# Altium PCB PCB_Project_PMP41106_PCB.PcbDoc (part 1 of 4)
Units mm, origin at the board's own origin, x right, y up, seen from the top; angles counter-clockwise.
Board outline 190 x 100 mm, 2 copper layers (Top Layer, Bottom Layer), stack 1.646 mm thick; 219 components, 122 nets, 541 pads, 61 vias.
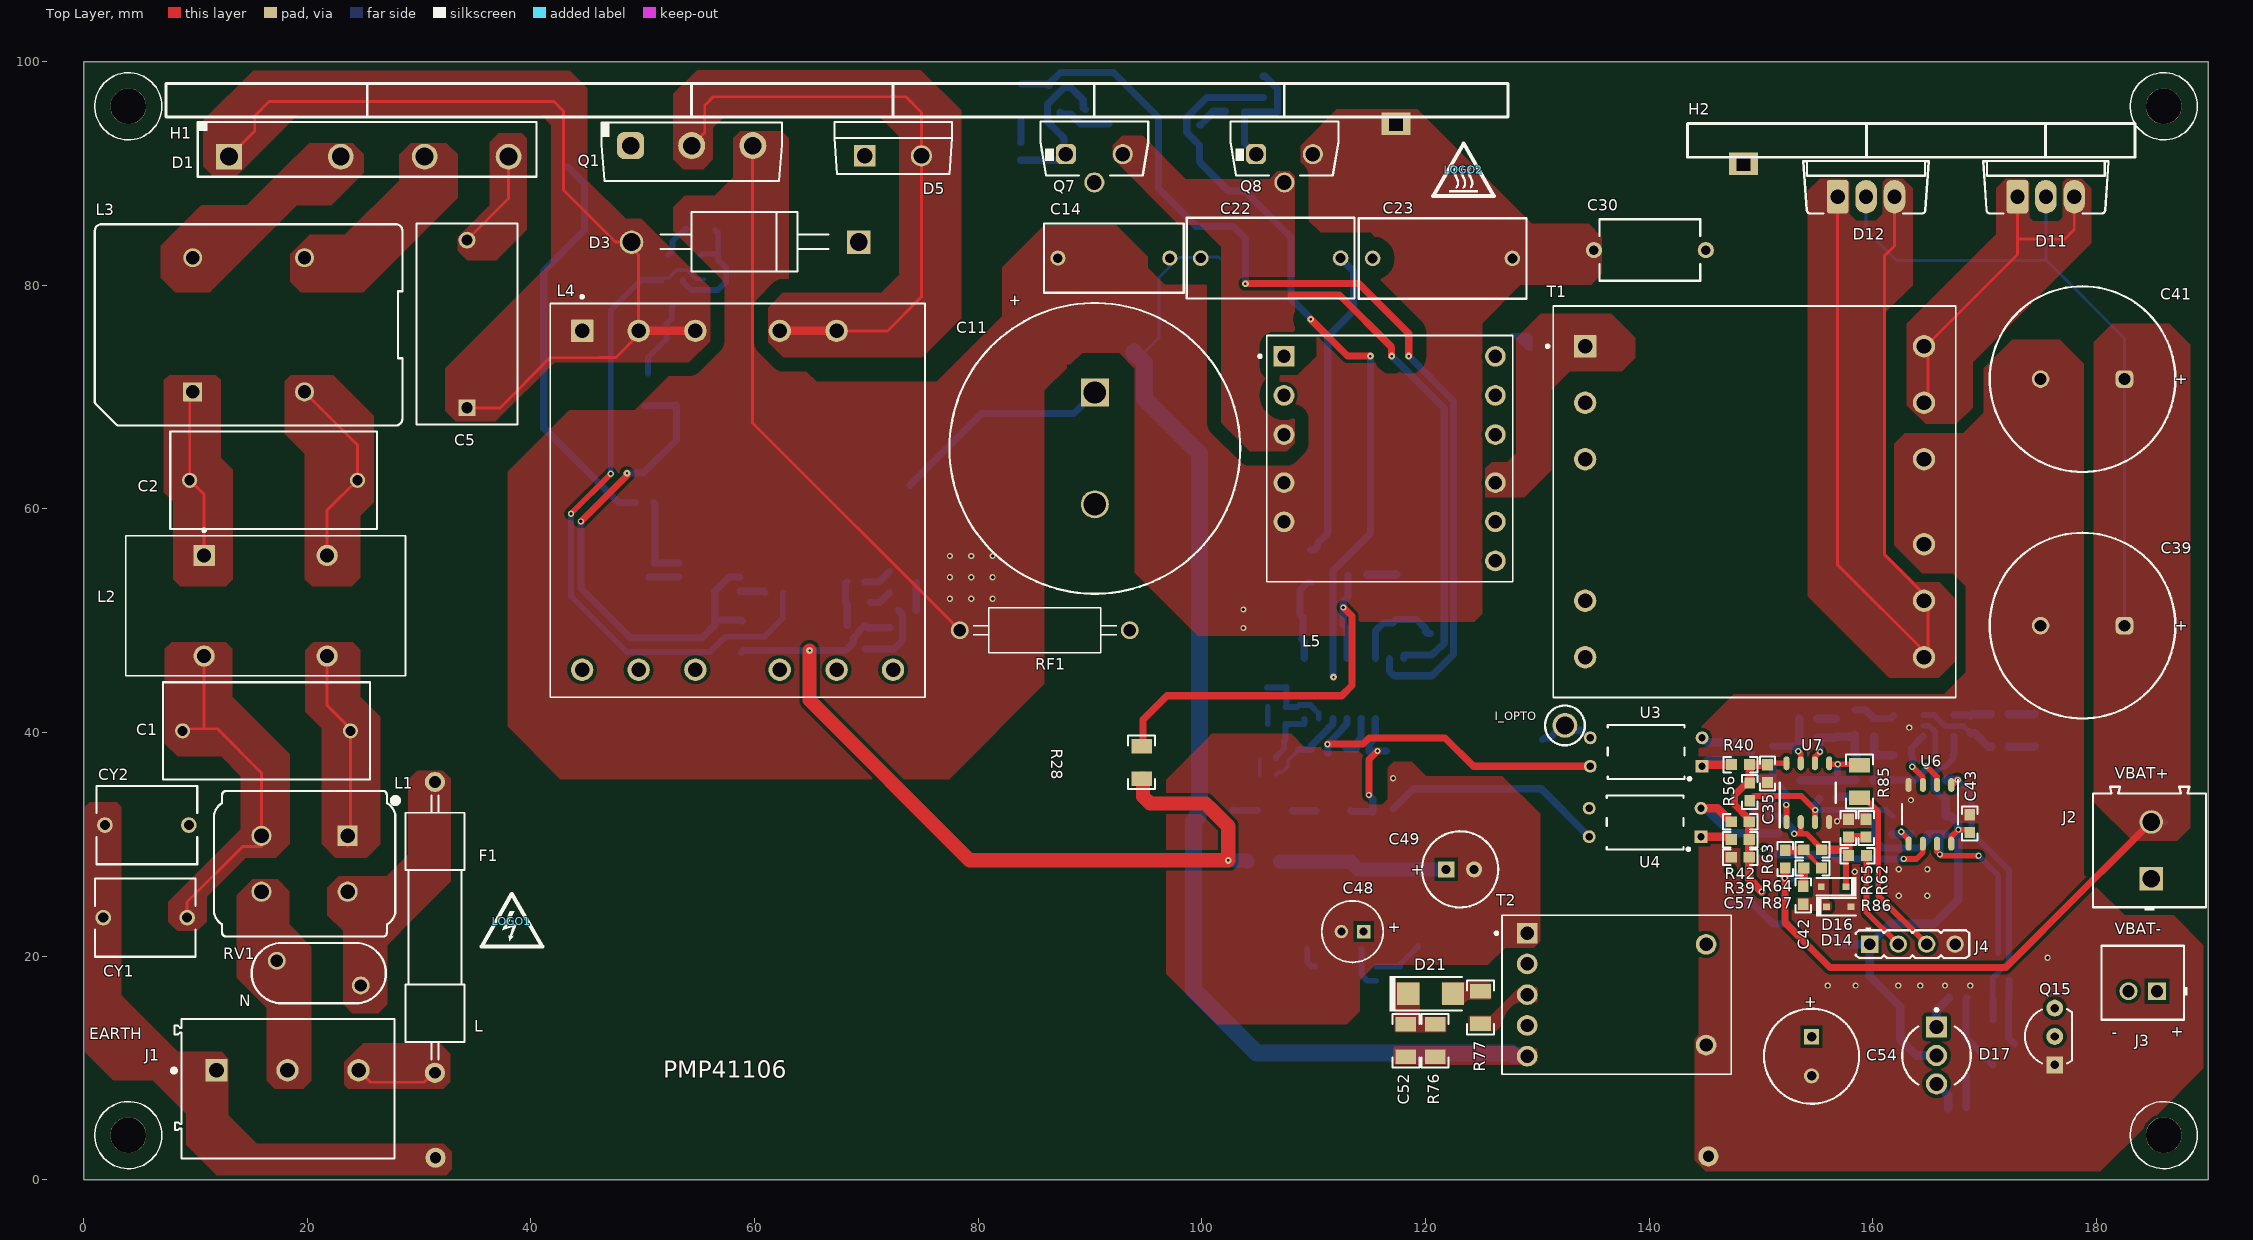
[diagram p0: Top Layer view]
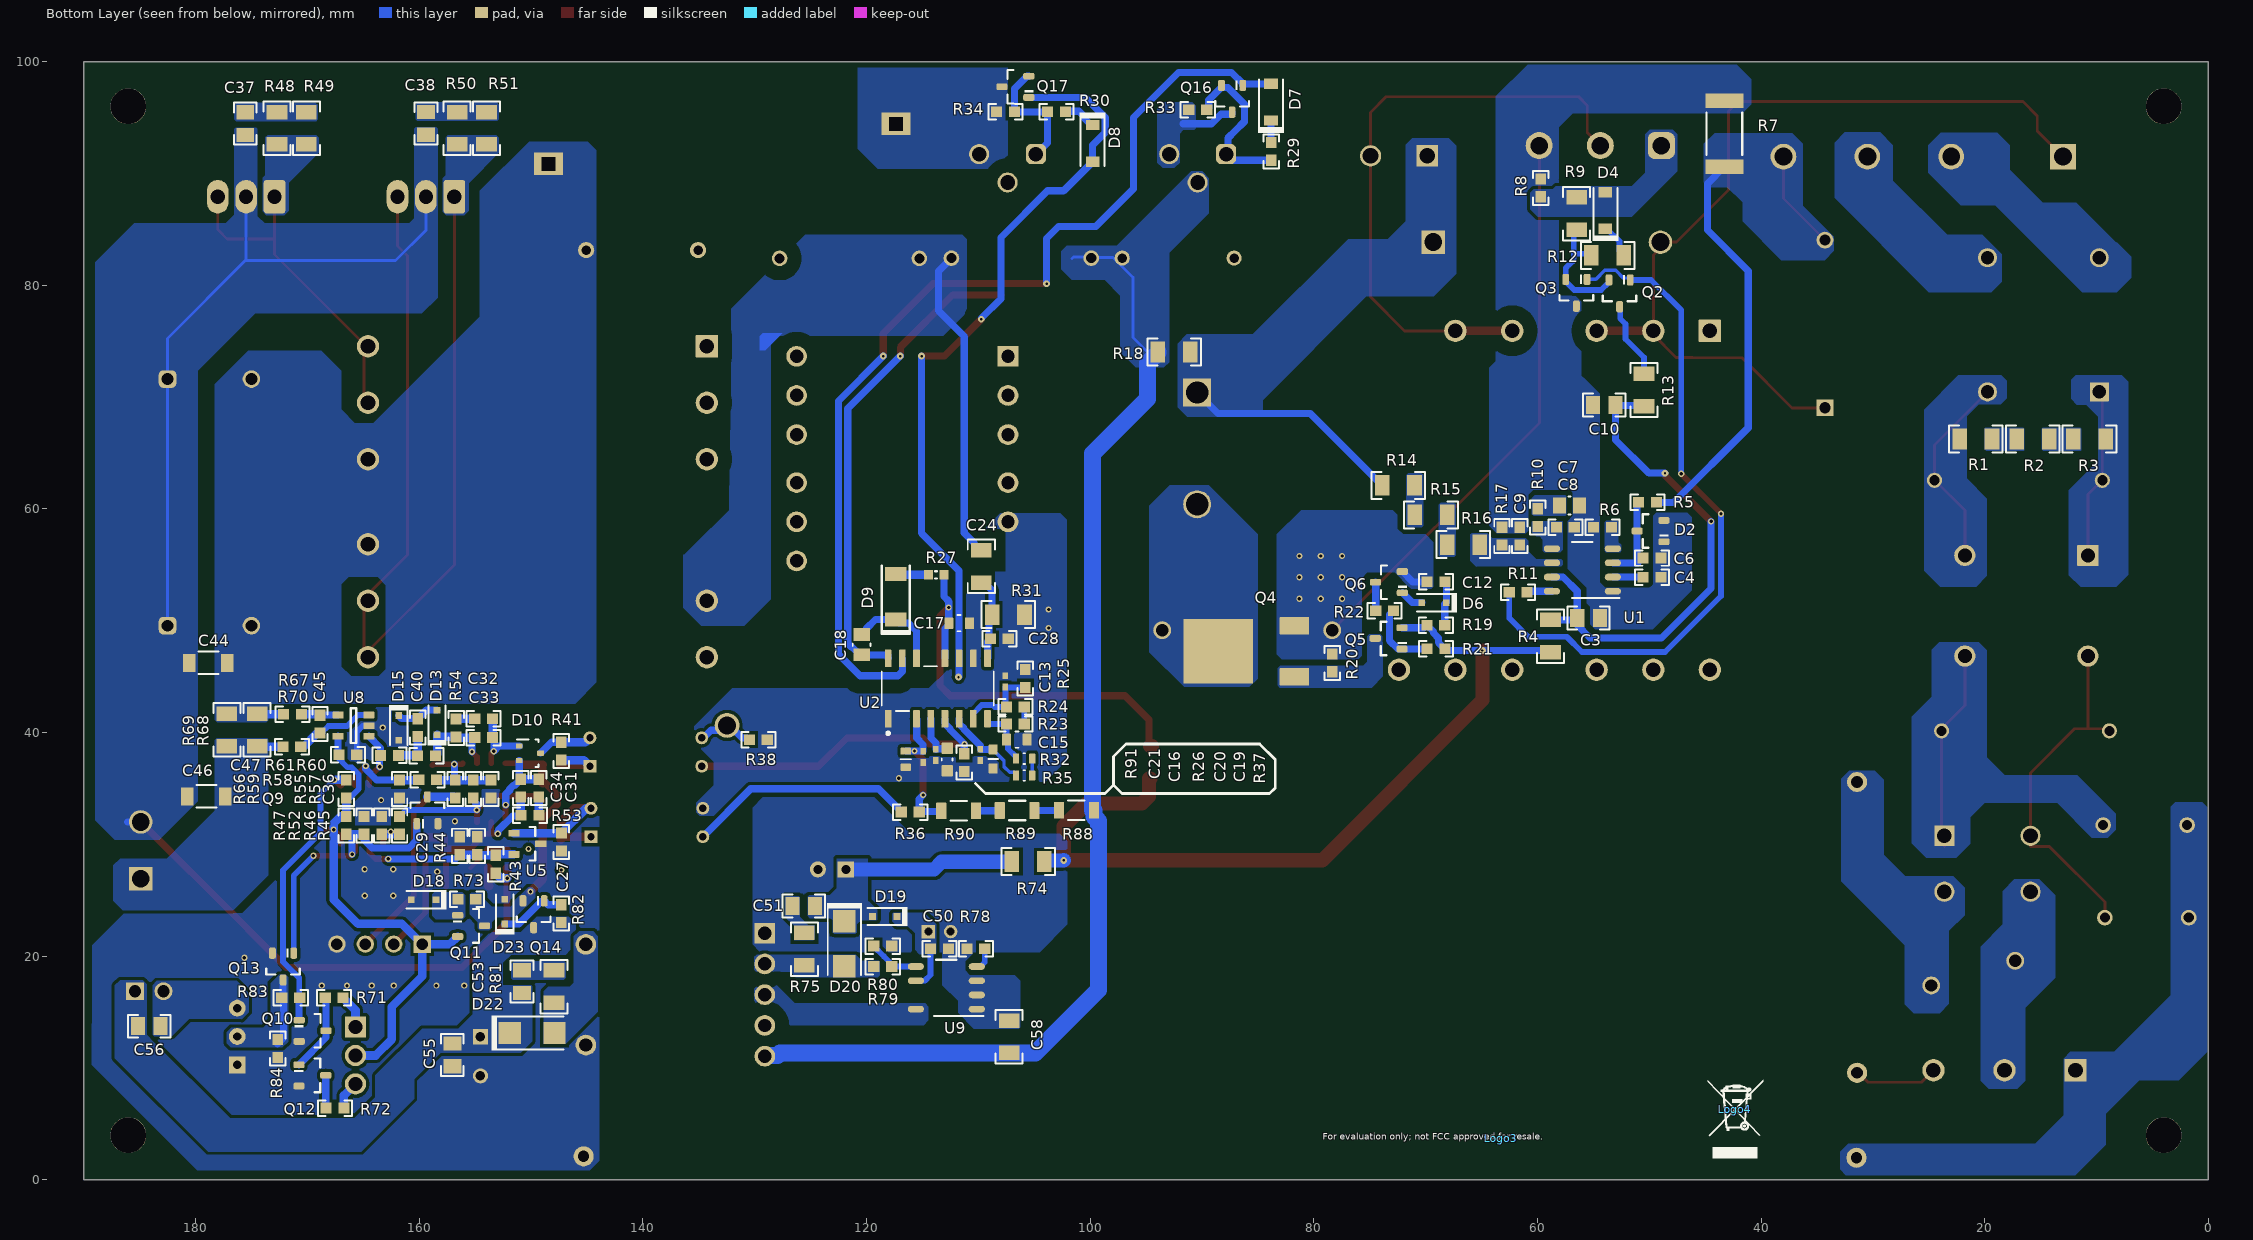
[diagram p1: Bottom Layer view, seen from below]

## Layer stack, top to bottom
Top Solder: solder mask 0.0102, Solder Resist, Dk 3.5
Top Layer: signal copper 0.0711
Dielectric1: core 1.5037, FR-4, Dk 4.8
Bottom Layer: signal copper 0.0711
Bottom Solder: solder mask 0.0102, Solder Resist, Dk 3.5

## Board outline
0,0 190,0 190,100 0,100

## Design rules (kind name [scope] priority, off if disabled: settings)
AcuteAngle [All] p1: minimum=4.50000000000000E+0001 checktracksonly=FALSE
AssemblyTestPointUsage [All] p1: valid=2
Clearance Clearance_3 [InNet('EARTH') vs Not InNet('EARTH') And Not InNet('12VS')] p1: gap=3.3 ignorepadtopadclearanceinfootprint=FALSE
Clearance Clearance_1 [InNetClass('HV') vs InNetClass('MV')] p2: gap=0.635 ignorepadtopadclearanceinfootprint=TRUE except(0: Arc-Hole Track-Hole SMDPad-Hole THPad-Hole Via-Hole Fill-Hole Poly-Hole Region-Hole Text-Hole)
Clearance Clearance_2 [InNetClass('HV') vs Not InNetClass('HV')] p3: gap=1.27 ignorepadtopadclearanceinfootprint=TRUE except(0: Arc-Hole Track-Hole SMDPad-Hole THPad-Hole Via-Hole Fill-Hole Poly-Hole Region-Hole Text-Hole; 1.016: Arc-THPad Track-THPad THPad-THPad)
Clearance Clearance_Keepouts [((IsTrack Or IsArc) And Not InPoly) And IsFree and IsKeepOut vs ((IsTrack Or IsArc) And Not InPoly) And IsFree and IsKeepOut] p4: gap=0 ignorepadtopadclearanceinfootprint=FALSE
Clearance Clearance_BoardEdge_MountingHoles [OnCopper and InComponentClass('Mounting Holes') vs IsKeepOut] p5: gap=1.016 ignorepadtopadclearanceinfootprint=FALSE except(0: Arc-Hole Track-Hole SMDPad-Hole THPad-Hole Via-Hole Fill-Hole Poly-Hole Region-Hole Text-Hole)
Clearance Clearance_BoardEdge_Poly [OnCopper and InPoly vs IsKeepOut] p6: gap=0.635 ignorepadtopadclearanceinfootprint=FALSE except(0: Arc-Hole Track-Hole SMDPad-Hole THPad-Hole Via-Hole Fill-Hole Poly-Hole Region-Hole Text-Hole)
Clearance Clearance_BoardEdge [OnCopper and Not InComponentClass('Logo') and not InComponentClass('FiducialMark') and not InRegion(1000,500,4000,800) and Not IsKeepout vs IsKeepOut] p7: gap=1.905 ignorepadtopadclearanceinfootprint=FALSE except(0: Arc-Hole Track-Hole SMDPad-Hole THPad-Hole Via-Hole Fill-Hole Poly-Hole Region-Hole Text-Hole)
Clearance Clearance_Poly [InPolygon] p8: gap=0.305 ignorepadtopadclearanceinfootprint=FALSE
Clearance [All] p9: gap=0.2 ignorepadtopadclearanceinfootprint=FALSE except(0: Arc-Hole Track-Hole SMDPad-Hole THPad-Hole Via-Hole Fill-Hole Poly-Hole Region-Hole Text-Hole)
ComponentClearance ComponentClearance_MountingHoles_FiducialMarks [InComponentClass('Mounting Holes') vs InComponentClass('FiducialMark')] p1: gap=0.508 collisioncheckmode=3 verticalgap=0.254 showdistances=FALSE
ComponentClearance ComponentClearance_Shunt [InComponentClass('Header') vs InComponentClass('Shunt')] p2: gap=0 collisioncheckmode=3 verticalgap=0 showdistances=FALSE
ComponentClearance ComponentClearance_Logo [InComponentClass('Logo')] p3: gap=0.127 collisioncheckmode=3 verticalgap=0.254 showdistances=FALSE
ComponentClearance ComponentClearance_ScrewToNut [(HasFootprint('NY PMS 440 0025 PH')) vs (HasFootprint('Keystone_1902C'))] p4: gap=0.508 collisioncheckmode=3 verticalgap=2540 showdistances=FALSE
ComponentClearance ComponentClearance_MountingHoles [InComponentClass('Mounting Holes')] p5: gap=0.508 collisioncheckmode=3 verticalgap=0.254 showdistances=FALSE
ComponentClearance ComponentClearance_SmallPassives [HasFootprint('0201*') or HasFootprint('0402*') or HasFootprint('0508') or HasFootprint('0603*') or HasFootprint('0612') or HasFootprint('0805*') or HasFootprint('0815*') or HasFootprint('0830*') or HasFootprint('1206*') or HasFootprint('1210*') or HasFootprint('1808*') or HasFootprint('1812*') or HasFootprint('1825*') or HasFootprint('2010*') or HasFootprint('2220*') or HasFootprint('2225*') or HasFootprint('2512*') or HasFootprint('2728*') or HasFootprint('3518*') vs HasFootprint('0201*') or HasFootprint('0402*') or HasFootprint('0508') or HasFootprint('0603*') or HasFootprint('0612') or HasFootprint('0805*') or HasFootprint('0815*') or HasFootprint('0830*') or HasFootprint('1206*') or HasFootprint('1210*') or HasFootprint('1808*') or HasFootprint('1812*') or HasFootprint('1825*') or HasFootprint('2010*') or HasFootprint('2220*') or HasFootprint('2225*') or HasFootprint('2512*') or HasFootprint('2728*') or HasFootprint('3518*')] p6: gap=0.508 collisioncheckmode=3 verticalgap=0.508 showdistances=FALSE
ComponentClearance ComponentClearance_THtoSMT [IsThruComponent vs IsSMTComponent] p7: gap=0.254 collisioncheckmode=3 verticalgap=0.254 showdistances=FALSE
ComponentClearance ComponentClearance_THtoTH [IsThruComponent vs IsThruComponent] p8: gap=0.254 collisioncheckmode=3 verticalgap=0.254 showdistances=FALSE
ComponentClearance [All] p9: gap=0.254 collisioncheckmode=3 verticalgap=0.254 showdistances=FALSE
DiffPairsRouting [All] p1: maxlimit=2.54 minlimit=0.254 mostfreqgap=0.254 toplayer_minwidth=0.381 toplayer_maxwidth=0.381 toplayer_prefwidth=0.381 bottomlayer_minwidth=0.381 bottomlayer_maxwidth=0.381 bottomlayer_prefwidth=0.381 maxuncoupledlength=25.4
FabricationTestPointUsage TestPointUsage [All] p1: valid=2 allowmultiple=FALSE
FabricationTestpoint Testpoint [All] p1: side=3 testpointundercomponent=TRUE minsize=1.016 maxsize=2.54 preferedsize=1.524 minholesize=0 maxholesize=1.016 preferedholesize=0.813 testpointgrid=0.025 allowsidetop=TRUE allowsidebottom=TRUE usegrid=TRUE gridtolerance=0
FanoutControl Fanout_LCC [IsLCC] p1: bgadir=Out bgaviamode=Centered fanoutstyle=Auto fanoutdirection=Alternating viagrid=0.025 // Fanout_LCC (Default Rule)
FanoutControl Fanout_BGA [IsBGA] p2: bgadir=Out bgaviamode=Centered fanoutstyle=Auto fanoutdirection=Alternating viagrid=0.025 // Fanout_BGA (Default Rule)
FanoutControl Fanout_Default [All] p4: bgadir=Out bgaviamode=Centered fanoutstyle=Auto fanoutdirection=Alternating viagrid=0.025 // Fanout_Default (Default Rule)
FanoutControl Fanout_Small [(CompPinCount < 5)] p5: bgadir=Out bgaviamode=Centered fanoutstyle=Auto fanoutdirection=OutThenIn viagrid=0.025 // Fanout_Small (Default Rule)
Height [All] p1: minheight=0 maxheight=76.2 prefheight=12.7
HoleSize [All] p1: absolutevalues=TRUE maxlimit=6.375 minlimit=0.178 maxpercent=80.000 minpercent=20.000
MinimumAnnularRing MinimumAnnularRing_ThermalPadVias [IsVia and InAnyComponent] p1: minimumring=0.15
MinimumAnnularRing [All] p2: minimumring=0.124
MinimumSolderMaskSliver MinimumSolderMaskSliver_Logo [InComponentClass('Logo') vs InComponentClass('Logo')] p1: minsoldermaskwidth=0.018
MinimumSolderMaskSliver [All] p2: minsoldermaskwidth=0.051
PlaneConnect [All] p1: planeconnectstyle=Direct reliefexpansion=0.254 reliefentries=4 reliefconductorwidth=0.254 reliefairgap=0.254
PolygonConnect [All] p1: connectstyle=Direct reliefconductorwidth=0.254 reliefentries=4 polygonreliefangle="90 Angle" airgapwidth=0.254
RoutingVias ThermalPadVias [IsVia and InAnyComponent] p1: holewidth=0.2 width=0.5 viastyle="Through Hole" minholewidth=0.2 minwidth=0.5 maxholewidth=0.33 maxwidth=0.6
RoutingVias [All] p2: holewidth=0.406 width=0.864 viastyle="Through Hole" minholewidth=0.2 minwidth=0.508 maxholewidth=1.016 maxwidth=1.651
SilkToBoardRegionClearance [Not ((IsComment or IsDesignator) And (Hide <> 'False')) and not InRegion(1000,500,4000,800)] p1:
SilkToSilkClearance SilkToSilkClearance_Pb-FreeLogo [(HasFootprint('Pb-Free_Overlay_Medium') OR HasFootprint('Pb-Free_Overlay_Small')) vs (HasFootprint('Pb-Free_Overlay_Medium') OR HasFootprint('Pb-Free_Overlay_Small'))] p1: silktosilkclearance=0
SilkToSilkClearance [All] p2: silktosilkclearance=0.025
SilkToSolderMaskClearance "Silk to Solder Mask Opening" [All] p1: minsilkscreentomaskgap=0.025 clearancetoexposedcopper=FALSE
SolderMaskExpansion [All] p1: expansion=0.05 istentingtop=FALSE
Width [All] p1: maxlimit=2.54 minlimit=0.152 preferedwidth=0.254 checkconnectedcopper=TRUE
14 further rules are at their usual default settings.

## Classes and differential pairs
net class MV: NetR88_1
net class HV: HO HS "N Wire" NetC1_1 NetC1_2 NetC2_1 NetC2_2 NetC5_1 NetC11_1 NetC18_2 NetC22_2 NetC52_2 NetD1_2 NetD1_3 NetD5_2 NetD7_1 NetD21_2 NetF1_1 NetQ7_1 NetR77_1 VBUS
component class PCB_Project_PMP23464_BlankSheet: C13 C14 C15 C16 C17 C18 C19 C20 C21 C22 C23 C24 C27 C28 C29 C30 C31 C32 C33 C34 C35 C36 C37 C38 C39 C40 C41 C42 C43 C44 C45 C46 C47 D7 D8 D9 D10 D11 D12 D13 D14 D15 D16 D17 D18 H1 H2 I_OPTO J2 L5 Q7 Q8 Q9 Q10 Q11 Q12 Q16 Q17 R23 R24 R25 R26 R27 R28 R29 R30 R31 R32 R33 R34 R35 R36 R37 R38 R39 R40 R41 R42 R43 R44 R45 R46 R47 R48 R49 R50 R51 R52 R53 R54 R55 R56 R57 R58 R59 R60 R61 R62 R63 R64 R65 R66 R67 R68 R69 R70 R71 R72 R73 R87 R88 R89 R90 R91 T1 U2 U3 U4 U5 U6 U7 U8
component class PCB_Project_PMP23464_CoverSheet: C1 C2 C3 C4 C5 C6 C7 C8 C9 C10 C11 C12 CY1 CY2 D1 D2 D3 D4 D5 D6 F1 J1 L1 L2 L3 L4 Q1 Q2 Q3 Q4 Q5 Q6 R1 R2 R3 R4 R5 R6 R7 R8 R9 R10 R11 R12 R13 R14 R15 R16 R17 R19 R20 R21 R22 RF1 RV1 U1
component class PCB_Project_PMP23464_EVM_Hardware: C48 C49 C50 C51 C52 C53 C54 C55 C56 C57 C58 D19 D20 D21 D22 D23 J3 J4 LOGO1 LOGO2 Logo3 Logo4 Q13 Q14 Q15 R74 R75 R76 R77 R78 R79 R80 R81 R82 R83 R84 R85 R86 T2 U9
component class Header: J4

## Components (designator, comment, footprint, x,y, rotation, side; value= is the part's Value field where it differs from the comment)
C1 "R46KI347050P0K" Kemet_1800x850x1450 16.358,40.157 r180 top value=0.47uF
C2 "R46KI347050P0K" Kemet_1800x850x1450 16.993,62.56 r0 top value=0.47uF
C3 "C2012X7R1E475K125AB" 0805_HV 55.423,50.248 r180 bottom value=4.7uF
C4 "GRM1885C1H222JA01D" 0603 49.759,53.88 r180 bottom value=2200pF
C5 "ECW-FD2W125K" B32922_17.5mm 34.29,76.537 r90 top value=1.2uF
C6 "GRM1885C1H102FA01J" 0603 49.759,55.607 r180 bottom value=1000pF
C7 "08053C225KAT2A" 0805_150 57.125,60.306 r180 bottom value=4.7uF
C8 "C0603C105K3RACTU" 0603 57.506,58.35 r180 bottom value=0.68uF
C9 "GRM1885C1H271JA01D" 0603 61.595,57.563 r90 bottom value=270pF
C10 "C2012X7R1H225K125AC" 0805_HV 54.026,69.291 r0 bottom value=2.2uF
C11 "450HXG220MEFCSN25X40" HXG_2500x4000 90.424,65.412 r270 top value=220uF
C12 "GRM188R71E474KA12D" 0603 69.063,53.474 r0 bottom value=0.47uF
C13 "C1005C0G1H221F050BA" 0402L 107.569,44.577 r90 bottom value=220pF
C14 "ECW-F6223HL" ECWF_L_1250x620x1050 92.126,82.423 r180 top value=0.022uF
C15 "CGA4J1X7R1V225K125AC" FP-CGA4J1X7R1V225K125AC_0805-MFG 106.553,39.37 r0 bottom value=2.2µF
C16 "GRM155R61E222KA01D" 0402L 113.792,37.998 r270 bottom value=2200pF
C17 "CGA4J1X7R1V225K125AC" FP-CGA4J1X7R1V225K125AC_0805-MFG 111.709,49.784 r0 bottom value=2.2µF
C18 "08053C225KAT2A" 0805_150 120.421,47.854 r90 bottom value=2.2uF
C19 "GRM155R72A102KA01D" 0402L 109.804,37.998 r270 bottom value=1000pF
C20 "C0603C332K5RACTU" 0603 111.252,37.313 r270 bottom value=3300pF
C21 "04025C102JAT2A" 0402L 114.935,37.827 r270 bottom value=1000pF
C22 "ECW-H8223HA" WCAP-FTX2_1500x700x1250 106.145,82.423 r0 top value=0.022uF
C23 "ECW-H8223HA" WCAP-FTX2_1500x700x1250 121.514,82.398 r0 top value=0.022uF
C24 "GRM31A5C2J151JW01D" 1206 109.728,54.864 r270 bottom value=100pF
C27 "GRM188R71E224KA88D" 0603 147.269,30.207 r270 bottom value=0.22uF
C28 "GRM1885C1H101JA01D" 0603 108.115,48.387 r180 bottom value=100pF
C29 "C0603X104K3RACTU" 0603 156.362,29.877 r90 bottom value=0.1uF
C30 "C921U222MVVDBA7317" C900_9x13 140.056,83.141 r180 top value=2200pF
C31 "C0603X103K5RACTU" 0603 149.301,35.033 r270 bottom value=0.01uF
C32 "C0603X104K3RACTU" 0603 154.229,41.231 r0 bottom value=0.1uF
C33 "C0603C102K3GACTU" 0603 154.229,39.554 r180 bottom value=1000pF
C34 "C0603X471K5RACTU" 0603 150.901,35.033 r90 bottom value=470pF
C35 "C0603X104K3RACTU" 0603 150.571,36.329 r270 top value=0.1uF
C36 "C0603X104K3RACTU" 0603 153.568,34.957 r90 bottom value=0.1uF
C37 "CL21C101JECNNWC" 0805_HV 175.539,94.447 r90 bottom value=100pF
C38 "CL21C101JECNNWC" 0805_HV 159.385,94.469 r90 bottom value=100pF
C39 "EEUFS1K681" UES_1600x2500 178.74,49.562 r180 top value=680uF
C40 "C1608X7R1E224K080AC" 0603 160.122,40.443 r90 bottom value=0.22uF
C41 "EEUFS1K681" UES_1600x2500 178.74,71.609 r180 top value=680uF
C42 "C0603X103K1RACTU" 0603 153.772,25.451 r270 top value=0.01uF
C43 "C0603X104K3RACTU" 0603 168.656,31.858 r90 top value=0.1uF
C44 "GRM31CR72A105KA01L" 1206_180 178.841,46.235 r180 bottom value=1uF
C45 "C0603X104K3RACTU" 0603 168.859,40.748 r270 bottom value=0.1uF
C46 "GRM31CR72A105KA01L" 1206_180 179.019,34.297 r180 bottom value=1uF
C47 "C0603X104K3RACTU" 0603 166.37,38.005 r180 bottom value=0.1uF
C48 "25ML22MEFC5X5" ML_500x500 113.462,22.206 r180 top value=22uF
C49 "EEU-FM1E101" FM_630x1120 123.088,27.769 r0 top value=100uF
C50 "C1608X7R1E105K080AE" 0603 113.462,20.682 r180 bottom value=1uF
C51 "08051A471JAT2A" 0805_HV 125.603,24.492 r180 bottom value=470pF
C52 "GRM31BR72J222KW01L" 1206 118.237,12.453 r90 top value=2200pF
C53 "08051A471JAT2A" 0805_HV 150.8,17.736 r90 bottom value=470pF
C54 "EKZE250ELL221MHB5D" Chemi-Con_800x1150 154.508,11.056 r270 top value=220uF
C55 "GRM216R61E105KA12D" 0805_HV 157.023,11.183 r270 bottom value=1uF
C56 "GRM216R61E105KA12D" 0805_HV 184.125,13.748 r180 bottom value=1uF
C57 "C0603X104K3RACTU" 0603 148.133,28.861 r180 top value=0.1uF
C58 "GRM31BR72J222KW01L" 1206 107.239,12.802 r90 bottom value=2200pF
CY1 "DE6E3KJ222MN3A" E_900x700x900 5.512,23.451 r0 top value=2200pF
CY2 "DE6E3KJ222MN3A" E_900x700x900 5.664,31.731 r180 top value=2200pF
D1 "GBJ2506-BP" GBJ 25.502,91.497 r0 top value=600V
D2 "BAV23CLT1G" SOT-23 49.886,58.02 r0 bottom value=250V
D3 "1N5406" DO-201AD 59.157,83.852 r180 top value=600V
D4 "1N4148W-7-F" SOD-123 53.924,86.678 r90 bottom value=100V
D5 "C3D04060A" TO-220-F2 72.381,91.567 r0 top value=600V
D6 "MM3Z5V1ST1G" SOD-323 69.24,51.619 r0 bottom value=5.1V
D7 "PMEG3010EGWJ" SOD-123 83.82,96.368 r90 bottom value=30V
D8 "PMEG3010EGWJ" SOD-123 99.771,92.685 r270 bottom value=30V
D9 "ES1JAF" SMAF 117.373,52.146 r90 bottom value=600V
D10 "BAT54AWT-TP" SOT-323 150.089,38.157 r180 bottom value=30V
D11 "TST20L200CW C0G" TO-220AB 175.463,87.916 r0 top value=200V
D12 "TST20L200CW C0G" TO-220AB 159.385,87.916 r0 top value=200V
D13 "BAT43WS-7-F" SOD-323 158.394,40.901 r90 bottom value=30V
D14 "BAT43WS-7-F" SOD-323 156.947,24.435 r0 top value=30V
D15 "BAT43WS-7-F" SOD-323 161.823,40.418 r270 bottom value=30V
D16 "BAT43WS-7-F" SOD-323 156.489,26.213 r180 top value=30V
D17 "MT6224-AHRG-A" FP-MT6224-AHRG-A_RADIAL-MFG 165.684,11.125 r270 top
D18 "MM3Z5V6ST1G" SOD-323 159.588,25.051 r0 bottom value=5.6V
D19 "1N4148WX-TP" SOD-323 118.364,23.552 r0 bottom value=75V
D20 "ES1D-13-F" SMA 121.971,21.114 r270 bottom value=200V
D21 "US1M-13-F" SMA 120.447,16.644 r0 top value=1000V
D22 "ES1D-13-F" SMA 149.885,13.138 r180 bottom value=200V
D23 "BZX384-C11,115" SOD-323 152.349,23.984 r90 bottom value=11V
F1 "0216010.MXEP" FUSE_0216 31.42,22.581 r270 top
H1 "40mm*120mm" Heatsink1 7.366,95.028 r0 top
H2 "" Heatsink2 143.434,91.447 r0 top
I_OPTO "5012" Keystone5012 132.461,40.64 r0 top
J1 "1714968" Phoenix_1714968 18.237,9.804 r0 top
J2 "691216510002S" Wurth_691216510002 184.887,29.471 r90 top
J3 "705430001" Molex_0705430001 184.125,16.872 r180 top
J4 "22284043" Molex_0022284043 163.536,21.082 r0 top
L1 "744842932" WE-CMB_NiZn_S 19.761,28.27 r270 top value=32uH
L2 "YXBCM020013007C" FP-YXBCM020013007C_PTH_CHOKE_12MM5_25MM0-MFG 16.281,51.34 r90 top
L3 "7448040707" WE-CMBNC_L 14.757,76.461 r90 top value=7mH
L4 "MAG-3001497" FP-MAG-3001497_PTH12-MFG 58.482,60.768 r270 top value=340uH
L5 "MAG-3001500" FP-MAG-3001500_PTH12-MFG 116.789,64.497 r0 top value=58uH
LOGO1 "DANGER HIGH VOLTAGE" IEC_HighVoltage_Small 38.303,23.114 r0 top
LOGO2 "CAUTION HOT SURFACE" IEC_HotSurface_Small 123.393,90.329 r0 top
Logo3 "FCC disclaimer" FCC_disclaimer 63.271,3.708 r180 bottom
Logo4 "WEEE logo" WEEE_Minimum 42.342,6.299 r180 bottom
Q1 "IPW60R080P7XKSA1" TO-247 54.381,92.488 r0 top value=600V
Q2 "MMBT2222ALT1G" SOT-23 52.654,79.273 r270 bottom value="40 V"
Q3 "MMBT2907ALT1G" SOT-23 56.515,79.324 r270 bottom value="60 V"
Q4 "IPD60R180P7SAUMA1" DPAK 85.141,47.276 r0 bottom value=600V
Q5 "MMBT3906LT1G" SOT-23 73.304,48.419 r0 bottom value="40 V"
Q6 "MMBT3904LT1G" SOT-23 73.279,53.448 r0 bottom value="40 V"
Q7 "IPA60R170CFD7XKSA1" TO-220_FullPAK_Offset 90.381,91.726 r0 top value=600V
Q8 "IPA60R170CFD7XKSA1" TO-220_FullPAK_Offset 107.381,91.726 r0 top value=600V
Q9 "2N7002-7-F" SOT-23 159.258,33.052 r90 bottom value=60V
Q10 "2N7002-7-F" SOT-23 169.52,13.335 r180 bottom value=60V
Q11 "MMBT3904LT1G" SOT-23 155.346,22.714 r180 bottom value="40 V"
Q12 "2N7002-7-F" SOT-23 169.545,9.347 r180 bottom value=60V
Q13 "2N7002-7-F" SOT-23 172.161,19.075 r270 bottom value=60V
Q14 "MMBT3904LT1G" SOT-23 149.758,23.756 r270 bottom value="40 V"
Q15 "2N4401-AP" TO-92AP 176.251,12.827 r90 top value="40 V"
Q16 "BC858C-7-F" SOT-23 87.3,96.672 r270 bottom value="30 V"
Q17 "BC858C-7-F" SOT-23 106.68,97.739 r0 bottom value="30 V"
R1 "RC1206FR-07330KL" 1206 20.803,66.25 r0 bottom value=330k
R2 "RC1206FR-07330KL" 1206 15.697,66.25 r0 bottom value=330k
R3 "RC1206FR-07330KL" 1206 10.643,66.25 r0 bottom value=330k
R4 "RC1206JR-070RL" 1206 58.826,48.622 r90 bottom value=0
R5 "RC0603FR-07220RL" 0603 50.165,60.586 r180 bottom value=220
R6 "RC0603FR-0721K5L" 0603 54.178,58.376 r180 bottom value=21.5k
R7 "CSRN2512FK20L0" 2512 43.282,93.555 r90 bottom value=0.02
R8 "RC0603FR-0710KL" 0603 59.69,88.703 r270 bottom value=10.0k
R9 "RC1206FR-073R3L" 1206 56.49,86.399 r90 bottom value=3.30
R10 "RC0603FR-0711K5L" 0603 59.969,59.214 r270 bottom value=12.4k
R11 "RC0603FR-0710RL" 0603 61.722,52.534 r0 bottom value=10.0
R12 "RC1206FR-073R3L" 1206 53.721,82.677 r180 bottom value=3.30
R13 "RC1206FR-073R3L" 1206 50.47,70.637 r90 bottom value=3.30
R14 "RC1206FR-071ML" 1206 72.441,62.11 r0 bottom value=1.00Meg
R15 "RC1206FR-071ML" 1206 69.52,59.468 r0 bottom value=1.00Meg
R16 "RC1206FR-071ML" 1206 66.624,56.801 r0 bottom value=1.00Meg
R17 "RC0603FR-0739KL" 0603 63.17,57.563 r270 bottom value=39.0k
R18 "RC1206JR-070RL" 1206 92.481,74.022 r0 bottom value=0
R19 "RC0603FR-07100KL" 0603 69.088,49.587 r0 bottom value=100k
R20 "RC0603FR-0710KL" 0603 78.334,46.235 r270 bottom value=10.0k
R21 "RC0603FR-07100KL" 0603 69.063,47.479 r180 bottom value=100k
R22 "RC0603FR-07100KL" 0603 73.66,50.908 r180 bottom value=100k
R23 "RC0603JR-070RL" 0603 106.68,40.767 r0 bottom value=453k
R24 "RC0603FR-0751K1L" 0603 106.68,42.291 r180 bottom value=453k
R25 "RC0603FR-07357KL" 0603 105.791,44.831 r270 bottom value=150k
R26 "B57371V2474J060" FP-B57371V2474J060_0603-MFG 112.776,37.592 r90 bottom value=470k
R27 "ERJ-3RQF2R2V" 0603L 113.767,54.102 r0 bottom value=2.20
R28 "RC1206JR-070RL" 1206 94.615,37.338 r270 top value=0
R29 "RC0603FR-0722R1L" 0603 83.795,91.973 r270 bottom value=22.1
R30 "RC0603FR-0722R1L" 0603 102.997,95.504 r0 bottom value=22.1
R31 "RC1206FR-07221RL" 1206 107.315,50.546 r0 bottom value=221
R32 "MCT0603MD1004BP500" FP-MCT0603MD1004BP500_0603-MFG 105.901,37.663 r0 bottom value=340k
R33 "RC0603FR-0710KL" 0603 90.373,95.707 r180 bottom value=10.0k
R34 "RC0603FR-0710KL" 0603 107.569,95.504 r180 bottom value=10.0k
R35 "MCT0603MD1004BP500" FP-MCT0603MD1004BP500_0603-MFG 105.901,36.165 r180 bottom value=340k
R36 "RC0603FR-0751KL" 0603 116.078,32.893 r180 bottom value=51.0k
R37 "RC0603JR-07130KL" FP-RC0603JR-07130KL_0603-MFG 108.661,37.643 r90 bottom value=160k
R38 "RCG060310K0FKEA" 0603 129.667,39.37 r0 bottom value=10.0k
R39 "RC0603FR-073KL" 0603 148.133,30.436 r0 top value=3.00k
R40 "RC0603FR-076K04L" 0603 148.158,37.141 r0 top value=6.04k
R41 "RC0603FR-073KL" 0603 147.295,38.335 r90 bottom value=3.00k
R42 "RC0603FR-0710KL" 0603 148.133,32.011 r0 top value=10.0k
R43 "RC0603FR-07301KL" 0603 153.137,28.226 r270 bottom value=210k
R44 "RC0603FR-0710KL" 0603 154.788,29.877 r270 bottom value=10.0k
R45 "RC0603FR-075K1L" 0603 161.747,31.706 r90 bottom value=6.34k
R46 "RC0603FR-077K5L" 0603 163.347,31.706 r270 bottom value=7.50k
R47 "RC0603FR-075K1L" 0603 166.497,31.706 r90 bottom value=5.10k
R48 "RC1206FR-0710RL" 1206 172.695,94.037 r90 bottom value=10.0
R49 "RC1206FR-0710RL" 1206 170.078,94.037 r90 bottom value=10.0
R50 "RC1206FR-0710RL" 1206 156.591,94.037 r90 bottom value=10.0
R51 "RC1206FR-0710RL" 1206 153.975,94.037 r90 bottom value=10.0
R52 "RC0603FR-0710KL" 0603 164.922,31.706 r270 bottom value=10.0k
R53 "RC0603FR-0768KL" 0603 150.089,32.62 r180 bottom value=68.0k
R54 "RC0603FR-072K4L" 0603 156.693,40.418 r270 bottom value=2.40k
R55 "RC0603FR-07187RL" 0603 156.769,34.957 r90 bottom value=191
R56 "RC0603FR-073KL" 0603 148.996,34.703 r270 top value=3.00k
R57 "RC0603FR-072K4L" 0603 155.169,34.957 r270 bottom value=3.30k
R58 "RC0603FR-075K1L" 0603 159.233,35.77 r180 bottom value=5.10k
R59 "RC0603FR-07499RL" 0603 161.747,34.957 r90 bottom value=499
R60 "RC0603FR-072KL" 0603 159.334,37.929 r0 bottom value=2.00k
R61 "RC0603FR-0720RL" 0603 162.636,37.954 r180 bottom value=20.0
R62 "CRCW060312K4FKEA" 0603 159.385,31.452 r270 top value=9.31k
R63 "RC0603FR-0720RL" 0603 152.171,28.683 r270 top value=20.0
R64 "RC0603FR-07100KL" 0603 154.61,29.521 r180 top value=100k
R65 "RC0603FR-075K11L" 0603 157.81,31.452 r270 top value=13.0k
R66 "RC0603FR-071KL" 0603 166.522,34.957 r90 bottom value=1.00k
R67 "RC0603FR-0710RL" 0603 171.323,41.637 r0 bottom value=10.0
R68 "CSR1206FK10L0" 1206 174.473,40.24 r270 bottom value=0.006
R69 "CSR1206FK10L0" 1206 177.19,40.24 r270 bottom value=0.006
R70 "RC0603FR-0710RL" 0603 171.374,38.716 r0 bottom value=10.0
R71 "RC0603FR-07510RL" 0603 167.589,16.281 r180 bottom value=510
R72 "RC0603FR-07510RL" 0603 167.513,6.426 r180 bottom value=510
R73 "RC0603FR-073K6L" 0603 155.727,25.102 r0 bottom value=3.60k
R74 "RC1206JR-070RL" 1206 105.537,28.473 r0 bottom value=0
R75 "RC1206FR-0710RL" 1206 125.552,20.631 r270 bottom value=10.0
R76 "RC1206FR-07200KL" 1206 120.853,12.453 r270 top value=200k
R77 "RC1206FR-07200RL" 1206 124.917,15.424 r90 top value=200
R78 "RC0603FR-071K8L" 0603 110.211,20.657 r180 bottom value=1.80k
R79 "RC0603FR-0782KL" 0603 118.542,19.082 r0 bottom value=82.0k
R80 "RC0603FR-0730KL" 0603 118.542,20.911 r0 bottom value=30.0k
R81 "RC1206FR-0710RL" 1206 147.93,17.279 r90 bottom value=10.0
R82 "RC0603FR-073KL" 0603 147.295,23.806 r90 bottom value=3.00k
R83 "RC0603FR-071KL" 0603 171.475,16.281 r180 bottom value=1.00k
R84 "RC0603FR-0710KL" 0603 172.644,11.76 r90 bottom value=10.0k
R85 "RC1206FR-0710KL" 1206 158.801,35.624 r270 top value=10.0k
R86 "RC0603FR-0710KL" 0603 158.623,29.007 r180 top value=10.0k
R87 "RC0603FR-07150KL" 0603 154.61,27.889 r0 top value=150k
R88 "KTR18EZPF3304" FP-KTR18EZPF3304_1206-MFG 101.219,33.052 r180 bottom
R89 "KTR18EZPF3304" FP-KTR18EZPF3304_1206-MFG 106.528,33.027 r180 bottom
R90 "KTR18EZPF3304" FP-KTR18EZPF3304_1206-MFG 111.76,33.001 r180 bottom
R91 "ERA-3AEB3652V" FP-ERA-3AEB3652V_0603-MFG 116.484,37.617 r90 bottom value=35.2k
RF1 "EMC2-47RKI" EMC2 85.954,49.156 r180 top value=47
RV1 "S10K275E2" VAR_S10K275E2 21.031,18.491 r180 top value=275V
T1 "MAG-3001499" FP-MAG-3001499_PTH_XFRMR_36MM0_35MM0-MFG 149.414,60.64 r270 top
T2 "MAG-3001498" FP-MAG-3001498_PTH_XFRMR_20MM5_14MM2-MFG 137.084,16.561 r180 top
U1 "UCC28180DR" D0008A_N 55.982,54.54 r0 bottom
U2 "UCC256603DDBR" DDB0014A-MFG 113.614,43.936 r90 bottom
U3 "FOD817A" DIP-4 139.725,38.259 r180 top
U4 "FOD817A" DIP-4 139.624,31.96 r180 top
U5 "TL431LIAIDBZR" DBZ0003A_N 150.317,30.055 r180 bottom
U6 "LMV393IDR" D0008A_L 165.1,32.69 r270 top
U7 "TL103WAIDR" D0008A_L 154.178,34.627 r90 top
U8 "INA180A2IDBVR" DBV0005A_N 165.862,40.621 r0 bottom
U9 "UCC28910DR" D0007A_N 112.852,17.177 r0 bottom

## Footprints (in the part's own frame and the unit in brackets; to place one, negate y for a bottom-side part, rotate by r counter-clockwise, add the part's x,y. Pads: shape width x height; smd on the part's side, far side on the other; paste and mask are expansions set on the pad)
0402L [mm] "0402 from SM-752 data"
  rect 0.6x0.5 smd: 1(-0.5,0) 2(0.5,0)
  body extent -0.55,-0.3 0.55,0.3, height 0.6
0603 [mm] "0603 from SM-752 data"
  rect 1x0.95 smd: 1(-0.8,0) 2(0.8,0)
  silkscreen extent -1.52,-0.69 1.52,0.69, body extent -0.87,-0.47 0.87,0.47, height 1
0603L [mm] "0603 from SM-752 data"
  rect 0.8x0.85 smd: 1(-0.7,0) 2(0.7,0)
  silkscreen extent -0.07,-0.33 0.07,0.33, body extent -0.87,-0.47 0.87,0.47, height 1
0805_150 [mm] "0805 / 1.5 mm height"
  rect 1.15x1.45 smd: 1(-0.9,0) 2(0.9,0)
  silkscreen extent -0.1,-0.8 0.1,0.8, body extent -1.1,-0.72 1.1,0.72, height 1.5
0805_HV [mil] "0805 with 30mil clearance between pads"
  rect 50x63 smd: 1(-40,0) 2(40,0)
  silkscreen extent -74,-40 74,40, body extent -43,-29 43,29, height 57
1206 [mm] "1206 from SM-752 data"
  rect 1.3x1.85 smd: 1(-1.45,0) 2(1.45,0)
  silkscreen extent -2.4,-1.21 2.4,1.21, body extent -1.7,-0.9 1.7,0.9, height 1.35
1206_180 [mm] "1206_180"
  rect 1.1x1.6 smd: 1(-1.7,0) 2(1.7,0)
  silkscreen extent -0.9,-1 0.9,1, body extent -1.75,-0.95 1.75,0.95, height 1.8
2512 [mm] "Chip Resistor, Body 6.3x3.2mm, IPC Medium Density"
  rect 1.3x3.4 smd: 1(-2.95,0) 2(2.95,0)
  silkscreen extent -1.9,-1.6 1.9,1.6, body extent -3.22,-1.67 3.22,1.67, height 0.71
B32922_17.5mm [mm] "Epcos film capacitors, 15mm spacing"
  rect 1.5x1.5 hole 1: 1(-7.5,0)
  round 1.5 hole 1: 2(7.5,0)
  silkscreen extent -9,-4.5 9,4.5, body extent -9,-4.5 9,4.5, height 17.5
C900_9x13 [mm] "Kemet"
  round 1.45 hole 0.85: 1(-5,0) 2(5,0)
  silkscreen extent -4.5,-2.75 4.5,2.75, body extent -4.49,-2.75 4.49,2.75, height 12.96
Chemi-Con_800x1150 [mm] "TH, 2-Leads, Dia 8mm"
  rect 1.35x1.35 hole 0.85: 1(-1.75,0)
  round 1.35 hole 0.85: 2(1.75,0)
  silkscreen extent -4.25,-4.25 4.25,4.25, body extent -4.22,-4.24 4.24,4.24, height 13.01
D0007A_N [mm] "SOIC, 7-Leads, Body 4.9x3.9mm, Pitch 1.27mm, IPC Medium Density"
  oval 1.45x0.6 smd: 1(-2.725,1.905) 2(-2.725,0.635) 3(-2.725,-0.635) 4(-2.725,-1.905) 5(2.725,-1.905) 6(2.725,-0.635) 8(2.725,1.905)
  silkscreen extent -3.32,-2.5 1.1,2.52, body extent -3.01,-2.45 3.01,2.45, height 1.75
D0008A_L [mm] "SOIC, 8-Leads, Body 4.9x3.9mm, Pitch 1.27mm, IPC High Density"
  oval 1.25x0.55 smd: 1(-2.625,1.905) 2(-2.625,0.635) 3(-2.625,-0.635) 4(-2.625,-1.905) 5(2.625,-1.905) 6(2.625,-0.635) 7(2.625,0.635) 8(2.625,1.905)
  silkscreen extent -3.1,-2.5 0.9,2.5, body extent -3,-2.45 3,2.45, height 1.63
D0008A_N [mm] "SOIC, 8-Leads, Body 4.9x3.9mm, Pitch 1.27mm, IPC Medium Density"
  oval 1.45x0.6 smd: 1(-2.725,1.905) 2(-2.725,0.635) 3(-2.725,-0.635) 4(-2.725,-1.905) 5(2.725,-1.905) 6(2.725,-0.635) 7(2.725,0.635) 8(2.725,1.905)
  silkscreen extent -3.3,-2.5 0.9,2.5, body extent -3,-2.45 3,2.45, height 1.63
DBV0005A_N [mm] "SOT23, 5-Leads, Body 2.9x1.6mm, Pitch 0.95mm, Lead Span 2.8mm, IPC Medium Density"
  rrect17% 1x0.6 smd: 1(-1.375,0.95) 2(-1.375,0) 3(-1.375,-0.95) 4(1.375,-0.95) 5(1.375,0.95)
  silkscreen extent -0.25,-1.55 0.25,1.55, body extent -1.42,-1.46 1.42,1.46, height 1.09
DBZ0003A_N [mm] "SOT23, 3-Leads, Body 2.9x1.3mm, Pitch 0.95mm, Lead Span 2.4mm, IPC Medium Density"
  rrect17% 1x0.6 smd: 1(-1.2,0.95) 2(-1.2,-0.95) 3(1.2,0)
  silkscreen extent 0.2,-1.5 0.7,1.5, body extent -1.26,-1.46 1.26,1.46, height 0.98
DDB0014A-MFG [mm]
  rrect17% 1.55x0.6 smd paste+0 mask+0: 1(-2.7,4.445) 3(-2.7,1.905) 4(-2.7,0.635) 5(-2.7,-0.635) 6(-2.7,-1.905) 7(-2.7,-3.175) 8(-2.7,-4.445) 9(2.7,-4.445) 10(2.7,-3.175) 11(2.7,-1.905) 12(2.7,-0.635) 14(2.7,1.905) 15(2.7,3.175) 16(2.7,4.445)
  silkscreen extent -4.12,-5 2,5, body extent -3.01,-4.95 3.01,4.95, height 1.75
DIP-4 [mm] "DIP, 4-Leads, Body 6.86x4.83mm, Pitch 2.54mm"
  rect 1.15x1.15 hole 0.65: 1(-5,1.27)
  round 1.15 hole 0.65: 2(-5,-1.27) 3(5,-1.27) 4(5,1.27)
  silkscreen extent -4,-2.41 3.43,2.52, body extent -4.44,-2.41 4.4,2.41, height 5.59
DO-201AD [mm] "Vishay dimensions"
  rect 2.1x2.1 hole 1.6: 1(-10.16,0)
  round 2.1 hole 1.6: 2(10.16,0)
  silkscreen extent -7.47,-2.7 7.57,2.61, body extent -10.82,-2.74 10.82,2.61, height 5.33
DPAK [mm] "D-PAK, 3-Pads, Body 6.22x6.73mm (max), TO-252AA using nominal STEP model"
  rrect6% 2.6x1.6 smd: 1(-3.4,2.28) 3(-3.4,-2.28)
  rrect2% 6.2x5.8 smd paste-3: 2(3.4,0)
  body extent -3.86,-3.29 5.84,3.29, height 2.48
E_900x700x900 [mm] "TH, 2- Leads, Body 9x7mm, Pin Spacing 7.5mm"
  round 1.4 hole 0.9: 1(-3.75,0) 2(3.75,0)
  silkscreen extent -4.5,-3.5 4.5,3.5, body extent -4.49,-3.5 4.49,3.5, height 11.96
ECWF_L_1250x620x1050 [mm] "TH, 2-Leads, Body 12.5x6.2mm, Pin Spacing 10mm"
  round 1.35 hole 0.85: 1(-5,0) 2(5,0)
  silkscreen extent -6.25,-3.1 6.25,3.1, body extent -6.25,-3.1 6.25,3.1, height 10.5
EMC2 [mm] "Welwyn"
  round 1.6 hole 1.1: 1(-7.6,0) 2(7.6,0)
  silkscreen extent -6.42,-2 6.42,2, body extent -8.02,-2 8.02,2, height 3.98
FCC_disclaimer [mm]
FM_630x1120 [mm] "PANASONIC"
  rect 1.45x1.45 hole 0.787: 1(-1.25,0)
  round 1.45 hole 0.787: 2(1.25,0)
  silkscreen extent -3.4,-3.4 3.4,3.4, body extent -3.37,-3.39 3.4,3.39, height 12.71
FP-B57371V2474J060_0603-MFG [mm]
  rrect10% 1x1 smd paste+0 mask+0: 1(-1,0) 2(1,0)
  silkscreen extent -0.13,-0.48 0.13,0.48, body extent -0.8,-0.4 0.8,0.4, height 0.9
FP-CGA4J1X7R1V225K125AC_0805-MFG [mm]
  rrect13% 0.8x1.05 smd paste+0 mask+0: 1(-0.925,0) 2(0.925,0)
  silkscreen extent -0.15,-0.72 0.15,0.72, body extent -1,-0.63 1,0.63, height 1.45
FP-ERA-3AEB3652V_0603-MFG [mm]
  rrect15% 0.65x0.9 smd paste+0 mask+0: 1(-0.725,0) 2(0.725,0)
  silkscreen extent 0,-0.5 0,0.5, body extent -0.8,-0.4 0.8,0.4, height 0.55
FP-KTR18EZPF3304_1206-MFG [mm]
  rrect11% 0.9x1.5 smd paste+0 mask+0: 1(-1.55,0) 2(1.55,0)
  silkscreen extent -0.72,-0.87 0.72,0.87, body extent -1.6,-0.8 1.6,0.8, height 0.65
FP-MAG-3001497_PTH12-MFG [mm]
  rrect5% 2x2 hole 1.3 paste-1000 mask+0: 1(-15.15,-13.9)
  round 2 hole 1.3 paste-1000 mask+0: 2(-15.15,-8.85) 3(-15.15,-3.77) 4(-15.15,3.77) 5(-15.15,8.85) 7(15.15,13.9) 8(15.15,8.85) 9(15.15,3.77) 10(15.15,-3.77) 11(15.15,-8.85) 12(15.15,-13.9)
  silkscreen extent -18.32,-16.75 17.6,16.75, body extent -17.6,-16.76 17.6,16.76, height 34
FP-MAG-3001498_PTH_XFRMR_20MM5_14MM2-MFG [mm]
  rrect5% 1.85x1.85 hole 1.2 paste-1000 mask+0: 1(8,-5.5)
  round 1.85 hole 1.2 paste-1000 mask+0: 2(8,-2.75) 3(8,0) 4(8,2.75) 5(8,5.5) 6(-8,4.5) 7(-8,-4.5)
  silkscreen extent -10.25,-7.1 10.87,7.1, body extent -10.35,-7.2 10.35,7.2, height 0.25
FP-MAG-3001499_PTH_XFRMR_36MM0_35MM0-MFG [mm]
  rrect5% 2x2 hole 1.3 paste-1000 mask+0: 1(-13.9,-15.15)
  round 2 hole 1.3 paste-1000 mask+0: 2(-8.85,-15.15) 3(-3.8,-15.15) 5(8.85,-15.15) 6(13.9,-15.15) 7(13.9,15.15) 8(8.85,15.15) 9(3.8,15.15) 10(-3.8,15.15) 11(-8.85,15.15) 12(-13.9,15.15)
  silkscreen extent -17.5,-18.62 17.5,18, body extent -17.6,-18.1 17.6,18.1, height 0.25
FP-MAG-3001500_PTH12-MFG [mm]
  rrect5% 1.85x1.85 hole 1.2 paste-1000 mask+0: 1(-9.45,9.15)
  round 1.85 hole 1.2 paste-1000 mask+0: 2(-9.45,5.65) 3(-9.45,2.15) 4(-9.45,-2.15) 5(-9.45,-5.65) 7(9.45,-9.15) 8(9.45,-5.65) 9(9.45,-2.15) 10(9.45,2.15) 11(9.45,5.65) 12(9.45,9.15)
  silkscreen extent -11.72,-11 11,11, body extent -11.1,-11.1 11.1,11.1, height 0.25
FP-MCT0603MD1004BP500_0603-MFG [mm]
  rrect18% 0.55x0.9 smd paste+0 mask+0: 1(-0.725,0) 2(0.725,0)
  silkscreen extent -0.08,-0.48 0.08,0.48, body extent -0.77,-0.43 0.77,0.43, height 0.55
FP-MT6224-AHRG-A_RADIAL-MFG [mm]
  rrect5% 1.9x1.9 hole 1.25 paste-1000 mask+0: 1(-2.54,0)
  round 1.9 hole 1.25 paste-1000 mask+0: 2(0,0) 3(2.54,0)
  silkscreen extent -4.2,-3.07 2.6,3.07, body extent -3.72,-3.72 3.72,3.72, height 0.25
FP-RC0603JR-07130KL_0603-MFG [mm]
  rrect13% 0.9x0.8 smd paste+0 mask+0: 1(-0.85,0) 2(0.85,0)
  silkscreen extent 0,-0.45 0,0.45, body extent -0.8,-0.4 0.8,0.4, height 0.55
FP-YXBCM020013007C_PTH_CHOKE_12MM5_25MM0-MFG [mm]
  rrect5% 1.9x1.9 hole 1.25 paste-1000 mask+0: 1(4.5,5.5)
  round 1.9 hole 1.25 paste-1000 mask+0: 2(4.5,-5.5) 3(-4.5,-5.5) 4(-4.5,5.5)
  silkscreen extent -6.25,-12.5 6.87,12.5, body extent -6.35,-12.6 6.35,12.6, height 0.25
FUSE_0216 [mm] "LITTELFUSE"
  round 1.8 hole 1.041: 1(-13,0) 2(13,0)
  silkscreen extent -11.8,-2.65 11.8,2.65, body extent -13.32,-2.65 13.32,2.65, height 5.3
GBJ [mm] "Micro Commercial Components"
  rect 2.3x2.3 hole 1.6: 1(-12.5,0)
  round 2.3 hole 1.6: 2(-2.5,0) 3(5,0) 4(12.5,0)
  silkscreen extent -15.3,-1.8 15,3.1, body extent -15.25,-1.75 15.05,3.05, height 24.3
Heatsink1 [mm]
  rect 2.6x2 hole 1.2 square: 1(110,-0.6)
  silkscreen extent 0,0 120,3, body extent 0,0 120,3, height 40
Heatsink2 [mm]
  rect 2.6x2 hole 1.2 square: 1(5,-0.6)
  silkscreen extent 0,0 40,3, body extent 0,0 40,3, height 40
HXG_2500x4000 [mm] "TH, 2-Leads, Dia 25mm, Pin Spacing 10mm"
  rect 2.5x2.5 hole 2: 1(-5,0)
  round 2.5 hole 2: 2(5,0)
  silkscreen extent -13,-13 13,13, body extent -12.9,-12.97 13.1,12.97, height 42
IEC_HighVoltage_Small [mm]
  silkscreen extent -2.72,-2.24 2.72,2.47
IEC_HotSurface_Small [mm]
  silkscreen extent -2.72,-2.36 2.72,2.35
Kemet_1800x850x1450 [mm] "TH, 2-Leads, Body 18x8.5mm, Pin Spacing 15mm"
  round 1.35 hole 0.9: 1(-7.5,0) 2(7.5,0)
  silkscreen extent -9.25,-4.35 9.25,4.35, body extent -9.25,-4.35 9.25,4.35, height 14.6
Keystone5012 [mil] "Keystone Multipurpose loops"
  round 87 hole 63: 1(0,0)
  silkscreen extent -70,-70 70,70, body extent -63,-63 63,62, height 319
ML_500x500 [mm] "Rubycon"
  rect 1.2x1.2 hole 0.711: 1(-1,0)
  round 1.2 hole 0.711: 2(1,0)
  silkscreen extent -2.75,-2.75 2.75,2.75, body extent -2.73,-2.75 2.75,2.75, height 6.51
Molex_0022284043 [mm] "Header, 2.54mm, 4x1, TH"
  rect 1.55x1.55 hole 1.02: 1(-3.81,0)
  round 1.55 hole 1.02: 2(-1.27,0) 3(1.27,0) 4(3.81,0)
  silkscreen extent -5.08,-1.24 5.08,1.5, body extent -5.08,-1.24 5.08,1.24, height 8.4
Molex_0705430001 [mm] "Header(shrouded), 2.54mm, 2x1, TH"
  rect 1.6x1.6 hole 1.09: 1(-1.27,0)
  round 1.6 hole 1.09: 2(1.27,0)
  silkscreen extent -4,-4.06 3.68,2.54, body extent -3.68,-4.06 3.68,2.54, height 11.81
Phoenix_1714968 [mm] "Phoenix"
  rect 2x2 hole 1.3: 1(-6.35,0)
  round 2 hole 1.3: 2(0,0) 3(6.35,0)
  silkscreen extent -10.33,-7.88 9.57,4.6, body extent -10.06,-7.9 9.56,4.6, height 21.5
SMA [mm] "Molded Diode, 2-Leads, Body 4.3x2.6mm, IPC Medium Density, based on OnSemi component dimensions and land pattern"
  rect 2x2 smd: 1(-2,0) 2(2,0)
  silkscreen extent -3.66,-1.57 2.79,1.57, body extent -2.6,-1.3 2.6,1.3, height 2.42
SMAF [mm] "SMD, 2-Leads, Body 3.8x2.5mm"
  rect 1.24x1.89 smd: 1(-2.04,0) 2(2.04,0)
  silkscreen extent -3.4,-1.3 2.8,1.3, body extent -2.35,-1.25 2.35,1.25, height 1
SOD-123 [mm] "On Semi recommended land pattern"
  rect 0.915x1.22 smd: 1(-1.637,0) 2(1.637,0)
  silkscreen extent -2.74,-1.17 2.03,1.17, body extent -1.93,-0.9 1.93,0.9, height 1.35
SOD-323 [mm] "NXP recommended land pattern"
  rect 0.6x0.6 smd paste-0.05: 1(-1.1,0) 2(1.1,0)
  silkscreen extent -2.06,-0.86 1.53,0.86, body extent -1.3,-0.67 1.3,0.68, height 1.1
SOT-23 [mm] "SOT23, 3-Leads, Body 2.9x1.3mm, Pitch 0.95mm, Lead Span 2.5mm, IPC Medium Density"
  rrect50% 1x0.6 smd: 1(-1.2,0.95) 2(-1.2,-0.95) 3(1.2,0)
  silkscreen extent -1.62,-1.5 0.7,1.5, body extent -1.16,-1.45 1.21,1.45, height 1
SOT-323 [mm] "Diodes Inc recommended land pattern.  2016-02-24"
  rrect21% 0.6x0.47 smd: 1(-0.95,0.65) 2(-0.95,-0.65) 3(0.95,0)
  silkscreen extent -1.14,-1.22 0.77,1.22, body extent -1.13,-1.13 1.12,1.12, height 1.13
TO-92AP [mm] "TO, Flat Index; 3 In-Line, Axial Leads; Body Dia. 5mm; Leads 0.55 x 0.50 mm (max)"
  rect 1.5x1.5 hole 0.75: 1(-2.54,0)
  round 1.5 hole 0.75: 2(0,0) 3(2.54,0)
  silkscreen extent -2.42,-1.53 2.44,2.66, body extent -2.87,-1.53 2.87,2.66, height 9.33
TO-220-F2 [mm] "CREE"
  rect 1.9x1.9 hole 1.4: 1(-2.54,0)
  round 1.9 hole 1.4: 2(2.54,0)
  silkscreen extent -5.25,-1.64 5.26,3.01, body extent -5.25,-1.64 5.26,3.01, height 19.09
TO-220_FullPAK_Offset [mm] "Infineon  PG-TO220-3-31"
  rrect50% 1.8x1.8 hole 1.3: 1(-2.54,0)
  round 1.8 hole 1.3: 2(0,-2.54) 3(2.54,0)
  silkscreen extent -4.82,-1.91 4.83,2.92, body extent -4.82,-2.84 4.83,2.92, height 22.91
TO-220AB [mm] "Copied from Altium's version of TO3B"
  rrect25% 1.93x3 hole 1.27: 1(-2.54,0)
  oval 1.93x3 hole 1.27: 2(0,0) 3(2.54,0)
  silkscreen extent -5.61,-1.49 5.61,3.2, body extent -5.61,-1.49 5.61,3.2, height 19.42
TO-247 [mil] "Standard TO-247"
  rrect50% 95x95 / inner round 78 / far side rrect50% 95x95 hole 62: 1(-215,0)
  round 95 / inner round 78 / far side round 95 hole 62: 2(0,0) 3(215,0)
  silkscreen extent -318,-124 318,81, body extent -318,-124 318,81, height 1007
UES_1600x2500 [mm] "TH, 2-Leads, Dia 16mm, Lead Spacing 7.5mm"
  rrect50% 1.575x1.575 hole 1.05: 1(-3.75,0)
  round 1.575 hole 1.05: 2(3.75,0)
  silkscreen extent -8.3,-8.3 8.3,8.3, body extent -8,-8 8.01,8, height 26.51
VAR_S10K275E2 [mm] "EPCOS"
  round 1.6 hole 1.1: 1(-3.75,1.1) 2(3.75,-1.1)
  silkscreen extent -6,-2.7 6,2.7, body extent -5.98,-2.7 5.98,2.7, height 14.99
WCAP-FTX2_1500x700x1250 [mm] "TH, 2-Leads, Body 15x7mm, Pin Spacing 12.5mm"
  round 1.4 hole 0.9: 1(-6.25,0) 2(6.25,0)
  silkscreen extent -7.5,-3.6 7.5,3.6, body extent -7.5,-3.5 7.5,3.5, height 12.3
WE-CMB_NiZn_S [mm] "TH, 4-Leads, Body 18.5x14.5mm"
  rect 1.8x1.8 hole 1.3: 1(-2.5,3.85)
  round 1.8 hole 1.3: 2(2.5,3.85) 3(2.5,-3.85) 4(-2.5,-3.85)
  silkscreen extent -6.5,-8.1 6.5,8.37, body extent -6.53,-8.09 6.52,8.09, height 19.55
WE-CMBNC_L [mm] "TH, 4-Leads, Body 19x28mm"
  rrect6% 1.7x1.7 hole 1.2: 1(-6,5)
  round 1.7 hole 1.2: 2(-6,-5) 3(6,-5) 4(6,5)
  silkscreen extent -9,-13.75 9,13.75, body extent -9,-13.75 9,13.75, height 25.47
WEEE_Minimum [mm] "WEEElie bin"
  silkscreen extent -2.42,-4.38 2.52,2.65
Wurth_691216510002 [mm] "Receptacle, 5.08mm, 2x1, TH"
  rect 2.1x2.1 hole 1.6: 1(-2.54,0)
  round 2.1 hole 1.6: 2(2.54,0)
  silkscreen extent -5.4,-4.9 5.68,5.2, body extent -5.1,-4.9 5.66,5.2, height 13.8

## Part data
C1 C2: library part CMP-0078590-1, "CAP, Film, 0.47 µF, X2 275 VAC, +/- 10%, TH", Cap_Case=18x8.5x14.5, Manufacturer=Kemet, Supplier Part Number 1=80-R46KI347050P0K, Tolerance_%=10%, ValueDisplayed=0.47µF
C3: library part CMP-0007870-2, "CAP, CERM, 4.7 uF, 25 V, +/- 10%, X7R, 0805", Cap_Case=0805, Manufacturer=TDK, Supplier Part Number 1=445-5972-1-ND, TempCo=X7R, Tolerance_%=10%, Value1=Unknown, Value2=25V, ValueDisplayed=4.7uF
C4: library part CMP-0007198-4, "CAP, CERM, 2200 pF, 50 V, +/- 5%, C0G/NP0, 0603", Cap_Case=0603, Manufacturer=MuRata, Supplier Part Number 1=490-1459-1-ND, TempCo=C0G/NP0, Tolerance_%=5%, Value1=Unknown, Value2=50V, ValueDisplayed=2200pF
C5: library part CMP-0012412-3, "CAP, Film, 1.2 uF, 450 V, +/- 10%, TH", Manufacturer="Panasonic Electronic Components", Supplier Part Number 1=495-6910-ND, Tolerance_%=10%, Value1=Unknown, Value2=450V, ValueDisplayed=1.2uF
